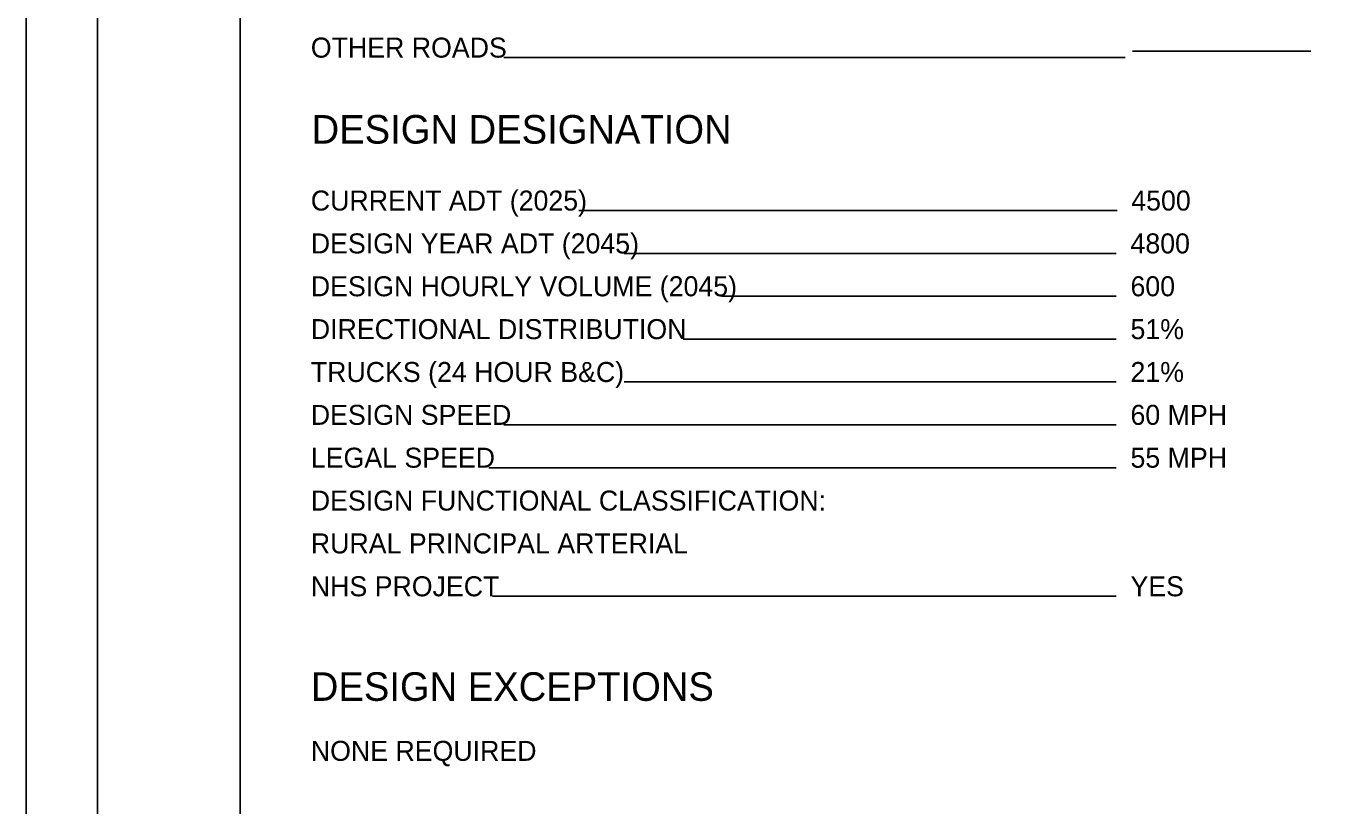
# Model space of a CAD drawing. Extents: x 0 to 34, y 0 to 22.
# Drawn here: x 0 to 9.16, y 5.64 to 11.1 of the extents above; entities that cross this region are included whole.
import ezdxf

# ---------------------------------------------------------------- set-up
doc = ezdxf.new("R2010")
doc.units = 0
for name, color, linetype in [('SH_Border', 7, 'Continuous'), ('SH_Cut_Line', 7, 'Continuous'), ('SH_Data', 7, 'Continuous'), ('SH_Text', 7, 'Continuous')]:
    doc.layers.add(name, color=color, linetype=linetype)

msp = doc.modelspace()

# ---------------------------------------------------------------- linework, layer by layer
at = {"layer": 'SH_Border'}
for points in [[(0.5, 21.5), (1.5, 21.5), (1.5, 0.5), (0.5, 0.5)], [(1.5, 21.5), (33.5, 21.5), (33.5, 0.5), (1.5, 0.5)]]:
    msp.add_lwpolyline(points, close=True, dxfattribs=at)
at = {"layer": 'SH_Cut_Line'}
msp.add_lwpolyline([(0, 0), (34, 0), (34, 22), (0, 22)], close=True, dxfattribs=at)
at = {"layer": 'SH_Data'}
for p, q in [((9, 10.9223), (7.75, 10.9223)), ((7.7, 10.8767), (3.3471, 10.8767)), ((7.6424, 9.8062), (3.871, 9.8062)), ((7.6368, 9.5062), (4.1885, 9.5062)), ((7.6368, 9.2062), (4.8723, 9.2062)), ((7.6368, 8.9062), (4.6037, 8.9062)), ((7.6368, 8.6062), (4.1885, 8.6062)), ((7.6368, 8.3062), (3.346, 8.3062)), ((7.6368, 8.0062), (3.2422, 8.0062)), ((7.6368, 7.1062), (3.2669, 7.1062))]:
    msp.add_line(p, q, dxfattribs=at)

# ---------------------------------------------------------------- texts
msp.add_text('DESIGN DESIGNATION', height=0.2, dxfattribs=at).set_placement((2, 10.2747))
at = {"layer": 'SH_Text'}
for s, height, p in [('OTHER ROADS', 0.14, (1.9944, 10.8767)), ('CURRENT ADT (2025)', 0.14, (1.9944, 9.8062)), ('4500', 0.14, (7.7424, 9.8062)), ('DESIGN YEAR ADT (2045)', 0.14, (1.9944, 9.5062)), ('4800', 0.14, (7.7368, 9.5062)), ('DESIGN HOURLY VOLUME (2045)', 0.14, (1.9944, 9.2062)), ('600', 0.14, (7.7368, 9.2062)), ('DIRECTIONAL DISTRIBUTION', 0.14, (1.9944, 8.9062)), ('51%', 0.14, (7.7368, 8.9062)), ('TRUCKS (24 HOUR B&C)', 0.14, (1.9944, 8.6062)), ('21%', 0.14, (7.7368, 8.6062)), ('DESIGN SPEED', 0.14, (1.9944, 8.3062)), ('60 MPH', 0.14, (7.7368, 8.3062)), ('LEGAL SPEED', 0.14, (1.9944, 8.0062)), ('55 MPH', 0.14, (7.7368, 8.0062)), ('DESIGN FUNCTIONAL CLASSIFICATION:', 0.14, (1.9944, 7.7062)), ('RURAL PRINCIPAL ARTERIAL', 0.14, (1.9944, 7.4062)), ('NHS PROJECT', 0.14, (1.9944, 7.1062)), ('YES', 0.14, (7.7368, 7.1062)), ('DESIGN EXCEPTIONS', 0.2, (1.9944, 6.3744)), ('NONE REQUIRED', 0.14, (1.9944, 5.9544))]:
    msp.add_text(s, height=height, dxfattribs=at).set_placement(p)

doc.saveas('drawing.dxf')
